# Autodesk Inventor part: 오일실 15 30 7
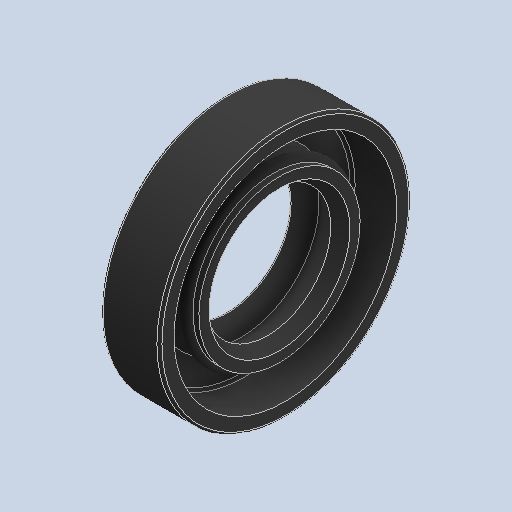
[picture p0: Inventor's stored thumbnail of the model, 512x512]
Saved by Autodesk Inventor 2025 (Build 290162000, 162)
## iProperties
Created: 2024-07
Part Number: 오일실 15 30 7
Material: 고무
Description: 오일-실
Document SubType Name: Modeling
Designer: myung
Density: 0.93 g/cm^3
Appearance: 기본값
Author: jhkim
Sending System: Autodesk Inventor 2025
Preprocessor: ST-DEVELOPER v20
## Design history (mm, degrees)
feature "Solid1"
node "솔리드1"
